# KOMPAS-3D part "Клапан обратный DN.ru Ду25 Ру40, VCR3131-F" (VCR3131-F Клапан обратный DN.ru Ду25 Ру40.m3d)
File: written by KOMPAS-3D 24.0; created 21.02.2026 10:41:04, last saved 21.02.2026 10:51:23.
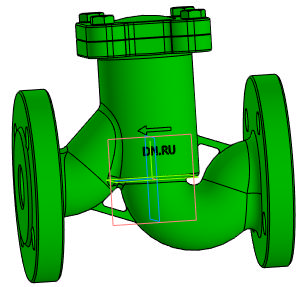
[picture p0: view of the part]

Document properties: Автор: R2D2; Полное имя файла: VCR3131-F Клапан обратный DN.ru Ду25 Ру40.cdw

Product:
- Body: Тело 2  | qty 1
    Масса: 5.543611
- Part/product: Клапан обратный DN.ru Ду25 Ру40  | designation VCR3131-F
    Масса: 4.6
    Раздел спецификации: Прочие изделия
    Форматы листов документа: A3
    Комментарий: D100-04038
    Примечание: D100-04038

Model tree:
1. Операция без истории:1

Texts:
  VCR3131-F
